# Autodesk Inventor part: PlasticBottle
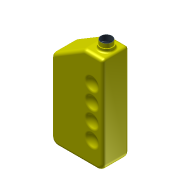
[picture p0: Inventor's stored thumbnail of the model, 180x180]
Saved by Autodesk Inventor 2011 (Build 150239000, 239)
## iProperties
Created: 2010-02
Part Number: PlasticBottle
Document SubType Name: Modeling
Designer: boganb
Density: 1 g/cm^3
Author: boganb
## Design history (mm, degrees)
sketch "Sketch1"
  geometry: L1 (-53.865, -86.816)-(47.735, -86.816); L2 (47.735, -86.816)-(47.735, 103.684); L3 (47.735, 103.684)-(9.635, 103.684); L4 (9.635, 103.684)-(-53.865, 65.584); L5 (-53.865, 65.584)-(-53.865, -86.816); 1 further point
  constraints: 10 end point, 3 perpendicular, 1 horizontal
  dimensions: "d0" = 152.4 distance of L4.end L1.start; "d1" = 190.5 distance of L1.end L2.end; "d2" = 101.6 distance of L1.start L1.end; "d3" = 38.1 distance of L2.end L3.end
extrude "Extrusion1" new body sketch "Sketch1" stored distance "d4" = 50.8; taper "d5" = 0 deg
sketch "Sketch2"
  geometry: L1 (0, 0)-(38.1, 0) reference; C1 r 12.7 at (19.05, 25.4); 2 further points
  constraints: 1 centre point, 1 midpoint, 1 vertical alignment
  dimensions: "d6" = 25.4 diameter of C1
extrude "Extrusion2" join sketch "Sketch2" distance "d7" = 6.35; taper "d8" = 0 deg
sketch "Sketch3"
  geometry: C1 r 12.7 at (0, 0) reference; C2 r 11.112 at (0, 0); 1 further point
  constraints: 1 centre point
  dimensions: "d9" = 1.5875 radial gap between concentric circles of C1 C2
extrude "Extrusion3" join sketch "Sketch3" distance "d10" = 7.9375; taper "d11" = 0 deg
workplane "Work Plane1"
sketch "Sketch4"
  geometry: L1 (0, 0)-(0, 152.4) reference; L2 (0, 0)-(50.8, 0) reference; L3 (-14.288, 63.5)-(-14.287, 25.4); A1 r 19.05 centre (-14.288, 44.45) between (-14.287, 25.4) and (-14.288, 63.5); 1 further point
  constraints: 2 end point, 2 point on circle, 1 centre point, 1 midpoint, 1 perpendicular
  dimensions: "d24" = 14.2875 distance between parallel lines of L3 L1; "d25" = 19.05 radius of A1; "d32" = 44.45 distance from line of A1.centre L2
revolve "Revolution1" sketch "Sketch4" stored, may be unused: angle "d26" = 180 deg
pattern_linear "Rectangular Pattern1" dims "d29" = 31.75
fillet "Fillet1" dims "d12" = 4.7625
fillet "Fillet4" dims "d16" = 12.7
fillet "Fillet5" dims "d17" = 12.7
fillet "Fillet2" dims "d13" = 6.35
fillet "Fillet3" dims "d14" = 3.175
fillet "Fillet6" dims "d30" = 6.35
mirror "Mirror1"
fillet "Fillet7" dims "d31" = 6.35
shell "Shell1" dims "d15" = 0.635
body "Solid1"
other parameters: "d18" = -22.225
